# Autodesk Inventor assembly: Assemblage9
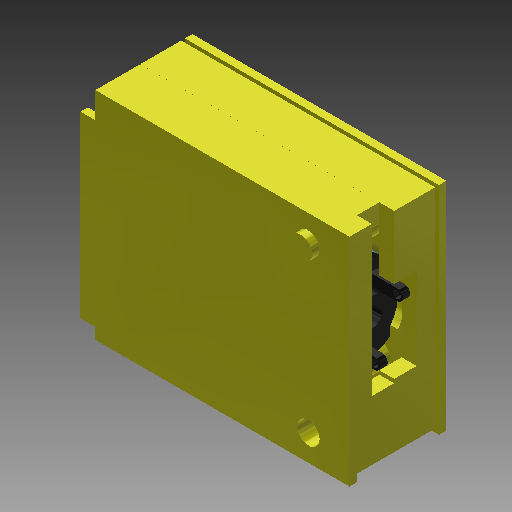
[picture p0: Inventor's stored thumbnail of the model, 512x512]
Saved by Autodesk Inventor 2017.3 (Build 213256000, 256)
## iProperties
Created: 2007-12
Part Number: Assemblage9
Material: Générique
Document SubType Name: Assembly
Designer: ficho
Author: ficho
Sending System: SolidWorks 2009
Last Author: christophe
Last Saved: 2011-02-10
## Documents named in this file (4)
- G:\travail\année 2019-2020\réforme\toussaint\Serrure biométrique SET\Documentations_pedagogique\Modelisation_Solidworks\Assemblage9.iam
- G:\travail\année 2019-2020\réforme\toussaint\Serrure biométrique SET\Documentations_pedagogique\Modelisation_Solidworks\Pièce31.ipt
- G:\travail\année 2019-2020\réforme\toussaint\Serrure biométrique SET\Documentations_pedagogique\Modelisation_Solidworks\Assemblage8.iam
- G:\travail\année 2019-2020\réforme\toussaint\Serrure biométrique SET\Documentations_pedagogique\Modelisation_Solidworks\Pièce30.ipt
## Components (3 placed, 3 different names)
1. Pièce31:1
2. Assemblage8:1 [sub-assembly]
3. Pièce30:1
